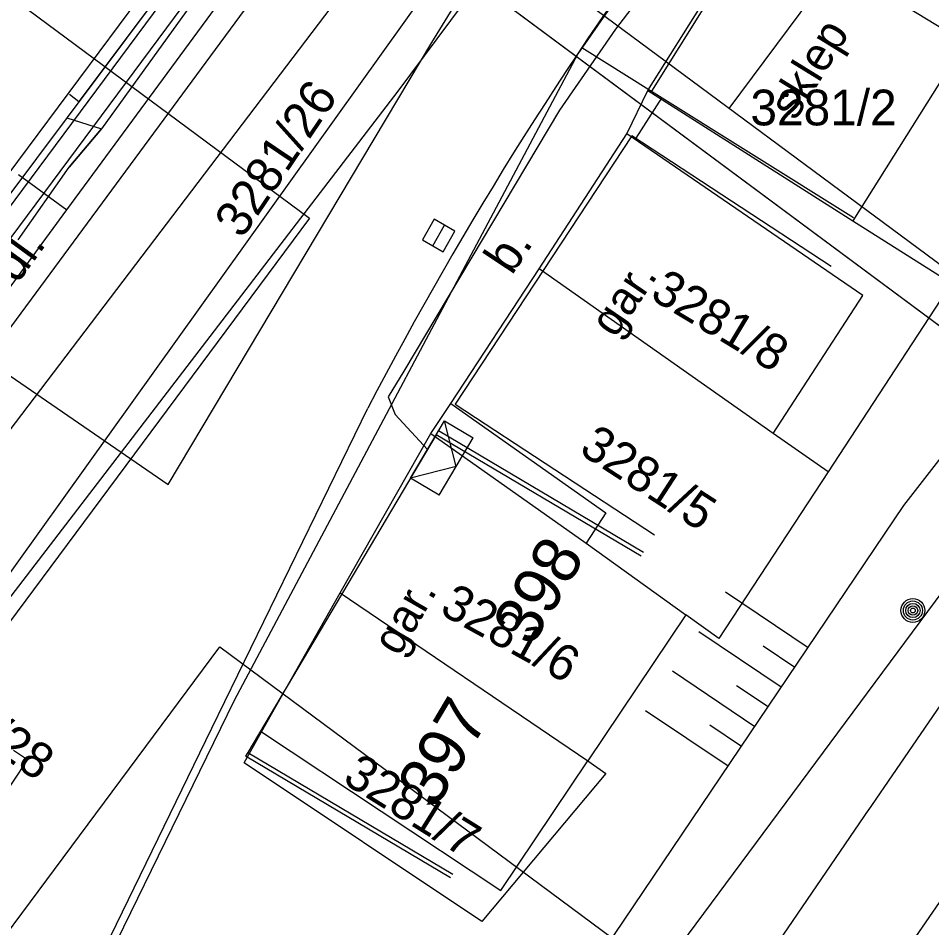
# Model space of a CAD drawing. Extents: x -601580 to 4, y -1204314 to 4.
# Drawn here: x -600277 to -600257.84, y -1203789.47 to -1203770.38 of the extents above; entities that cross this region are included whole.
import ezdxf

# ---------------------------------------------------------------- set-up
doc = ezdxf.new("R2010")
doc.units = 0
for name, color, linetype in [('00-EON NN', 7, 'Continuous'), ('00-INNOGY-NTL', 7, 'Continuous'), ('00-KN-HRANICE PARCEL', 7, 'Continuous'), ('00-KN-PARC. CISLA', 7, 'Continuous'), ('00-KN-VNITRNI KRESBA', 7, 'Continuous'), ('00-POLOHOPIS', 7, 'Continuous'), ('00-RAZÍTKO', 7, 'Continuous'), ('00-SITE KOM. KABEL', 7, 'Continuous'), ('00-VAK-KANAL-POTRUBI', 7, 'Continuous'), ('00-VAK-VODA-RAD IGIS', 7, 'Continuous'), ('11-REKONSTRUKCE KANALIZACE POPIS', 7, 'Continuous'), ('11-REKONSTRUKCE VODOVOD POPIS', 7, 'Continuous'), ('Vrstva 25', 7, 'Continuous'), ('Vrstva 27', 7, 'Continuous'), ('Vrstva 6', 7, 'Continuous'), ('Vrstva 9', 7, 'Continuous')]:
    doc.layers.add(name, color=color, linetype=linetype)

# ---------------------------------------------------------------- blocks, each defined once
blk = doc.blocks.new('6.30_50')
at = {"layer": 'Vrstva 27'}
blk.add_line((-0.25, 0), (0.25, 0), dxfattribs=at)
blk.add_lwpolyline([(-0.25, -0.25), (0.25, -0.25), (0.25, 0.25), (-0.25, 0.25)], close=True, dxfattribs=at)
blk = doc.blocks.new('6.01A_1056')
at = {"layer": 'Vrstva 25'}
for radius in [0.25, 0.2, 0.15, 0.1, 0.05]:
    blk.add_circle((0, 0), radius, dxfattribs=at)
blk = doc.blocks.new('VCHOD_1572')
at = {"layer": 'Vrstva 6'}
blk.add_line((0, 0.25), (0, 0), dxfattribs=at)
blk = doc.blocks.new('NN630')
at = {"layer": 'Vrstva 9'}
for points in [[(-3, -700), (-703, 0)], [(-703, -700), (-703, 0), (697, 0), (697, -700)], [(-3, -700), (697, 0)], [(-703, -700), (697, -700)]]:
    blk.add_lwpolyline(points, dxfattribs=at)

msp = doc.modelspace()

# ---------------------------------------------------------------- linework, layer by layer
at = {"layer": '00-EON NN'}
for points in [[(-600252.857, -1203744.996), (-600259.048, -1203754.786), (-600265.34, -1203759.062), (-600294.932, -1203798.94), (-600294.8, -1203799.42), (-600294.6, -1203799.71), (-600294.639, -1203800.117), (-600301.927, -1203809.794), (-600302.189, -1203809.81)], [(-600295.452, -1203798.97), (-600287.485, -1203788.234), (-600287.573, -1203788.171), (-600287.572, -1203787.922), (-600287.341, -1203787.853), (-600287.247, -1203787.913), (-600282.123, -1203781.008), (-600282.23, -1203780.938), (-600282.206, -1203780.697), (-600282.003, -1203780.612), (-600281.885, -1203780.687), (-600273.294, -1203769.109), (-600273.288, -1203768.864), (-600273.055, -1203768.788), (-600270.904, -1203765.889), (-600270.944, -1203765.611), (-600270.666, -1203765.567), (-600265.625, -1203758.774), (-600259.342, -1203754.503), (-600253.303, -1203744.952)], [(-600247.342, -1203745.533), (-600250.88, -1203751.15), (-600250.806, -1203751.444), (-600251.09, -1203751.45), (-600252.06, -1203752.67), (-600252.81, -1203753.78), (-600254.88, -1203757.09), (-600259.8, -1203764.05), (-600262.84, -1203768.48), (-600264.47, -1203770.61), (-600265.64, -1203772.31), (-600268.91, -1203777.79), (-600269.24, -1203778.33), (-600269.09, -1203778.7), (-600268.412, -1203779.43)]]:
    msp.add_lwpolyline(points, dxfattribs=at)
at = {"layer": '00-INNOGY-NTL'}
msp.add_line((-600276.99, -1203773.66), (-600275.98, -1203774.4), dxfattribs=at)
msp.add_lwpolyline([(-600295.95, -1203801.21), (-600295.65, -1203800.81), (-600287.36, -1203789.82), (-600286.53, -1203788.7), (-600278.7, -1203778.11), (-600278.55, -1203777.91), (-600275.98, -1203774.4), (-600270.38, -1203766.79), (-600268.42, -1203764.21), (-600266.21, -1203761.3), (-600264.99, -1203760.1), (-600261.02, -1203756.81), (-600258.4, -1203754.89), (-600252.86, -1203745.77), (-600247.26, -1203737.18), (-600244.78, -1203732.86), (-600245.17, -1203730.96), (-600245.99, -1203727.04), (-600245.48, -1203726.22)], dxfattribs=at)
at = {"layer": '00-KN-HRANICE PARCEL'}
for p, q in [((-600279.28, -1203776.44), (-600272.98, -1203767.97)), ((-600263.79, -1203771.9), (-600261.5, -1203768.23)), ((-600257.14, -1203770.89), (-600258.91, -1203769.81)), ((-600257.14, -1203770.89), (-600259.49, -1203774.63)), ((-600264.23, -1203772.81), (-600263.79, -1203771.9)), ((-600263.79, -1203771.9), (-600259.49, -1203774.63)), ((-600266.07, -1203775.64), (-600264.23, -1203772.81)), ((-600261.16, -1203779.1), (-600266.07, -1203775.64)), ((-600270.24, -1203782.44), (-600268.34, -1203779.1)), ((-600260.01, -1203779.9), (-600261.16, -1203779.1)), ((-600271.89, -1203785.36), (-600270.24, -1203782.44)), ((-600270.24, -1203782.44), (-600265.05, -1203785.97)), ((-600262.99, -1203782.9), (-600265.05, -1203785.97))]:
    msp.add_line(p, q, dxfattribs=at)
for points in [[(-600279.28, -1203776.44), (-600273.85, -1203780.17), (-600268.32, -1203770.89), (-600265.85, -1203766.87), (-600263.12, -1203761.89), (-600266.58, -1203759.37)], [(-600249.28, -1203766.8), (-600249.18, -1203771.13), (-600257.3, -1203781.99), (-600286.42, -1203821.27)], [(-600262.64, -1203767.37), (-600265.26, -1203771.13), (-600272.47, -1203784.7), (-600286.83, -1203814.12), (-600287.84, -1203817.36), (-600287.76, -1203819.53), (-600286.42, -1203821.27)], [(-600261.16, -1203779.1), (-600259.28, -1203776.2), (-600264.23, -1203772.81)], [(-600259.49, -1203774.63), (-600257.42, -1203775.94), (-600260.01, -1203779.9)], [(-600268.34, -1203779.1), (-600267.92, -1203778.47), (-600266.07, -1203775.64)], [(-600268.34, -1203779.1), (-600265.08, -1203781.4), (-600262.99, -1203782.9)], [(-600260.01, -1203779.9), (-600262.3, -1203783.4), (-600262.99, -1203782.9)], [(-600265.05, -1203785.97), (-600264.67, -1203786.23), (-600267.27, -1203789.34), (-600272.26, -1203786.01), (-600271.89, -1203785.36)], [(-600271.89, -1203785.36), (-600266.87, -1203788.69), (-600265.05, -1203785.97)]]:
    msp.add_lwpolyline(points, dxfattribs=at)
at = {"layer": '00-KN-VNITRNI KRESBA'}
for p, q in [((-600267.92, -1203778.47), (-600264.67, -1203780.76)), ((-600264.67, -1203780.76), (-600265.08, -1203781.4))]:
    msp.add_line(p, q, dxfattribs=at)
at = {"layer": '00-POLOHOPIS'}
for p, q in [((-600265.374, -1203760.864), (-600283.066, -1203784.884)), ((-600273.801, -1203769.554), (-600275.722, -1203772.126)), ((-600265.176, -1203770.997), (-600263.716, -1203771.909)), ((-600263.495, -1203772.043), (-600264.041, -1203772.895)), ((-600258.42, -1203780.606), (-600251.983, -1203772.323)), ((-600249.579, -1203773.011), (-600259.175, -1203787.013)), ((-600272.936, -1203785.282), (-600269.662, -1203778.567)), ((-600268.229, -1203779.122), (-600268.183, -1203779.044)), ((-600263.882, -1203781.593), (-600268.183, -1203779.044)), ((-600275.448, -1203805.851), (-600258.42, -1203780.606)), ((-600262.158, -1203782.422), (-600260.43, -1203783.587)), ((-600262.717, -1203783.251), (-600260.99, -1203784.416)), ((-600261.37, -1203783.556), (-600260.71, -1203784.001)), ((-600263.276, -1203784.08), (-600261.549, -1203785.245)), ((-600261.929, -1203784.385), (-600261.269, -1203784.83)), ((-600263.836, -1203784.909), (-600262.108, -1203786.074)), ((-600262.488, -1203785.214), (-600261.828, -1203785.659)), ((-600275.701, -1203790.96), (-600272.936, -1203785.282)), ((-600277.095, -1203785.743), (-600276.804, -1203785.937)), ((-600272.183, -1203785.795), (-600272.229, -1203785.872)), ((-600276.804, -1203785.937), (-600278.935, -1203789.149)), ((-600267.927, -1203788.421), (-600272.229, -1203785.872)), ((-600259.154, -1203786.982), (-600282.637, -1203821.382))]:
    msp.add_line(p, q, dxfattribs=at)
for points in [[(-600276.901, -1203765.244), (-600272.838, -1203768.264), (-600279.127, -1203776.684), (-600282.733, -1203773.992)], [(-600258.634, -1203769.979), (-600261.42, -1203768.237), (-600263.716, -1203771.909), (-600259.476, -1203774.56)], [(-600259.945, -1203775.593), (-600264.123, -1203772.846), (-600267.828, -1203778.48), (-600263.65, -1203781.227)], [(-600263.927, -1203781.671), (-600268.229, -1203779.122), (-600272.183, -1203785.795), (-600267.881, -1203788.344)]]:
    msp.add_lwpolyline(points, dxfattribs=at)
msp.add_arc((-600199.5, -1203815.029), 79.07, 143.00289, 152.54008, dxfattribs=at)
at = {"layer": '00-RAZÍTKO'}
for p, q in [((-600262.081, -1203772.278), (-600205.546, -1203696.113)), ((-600245.504, -1203784.583), (-600276.866, -1203761.304))]:
    msp.add_line(p, q, dxfattribs=at)
for points in [[(-600188.969, -1203708.417), (-600246.123, -1203785.417), (-600325.417, -1203726.559), (-600268.263, -1203649.56)], [(-600188.969, -1203708.417), (-600246.123, -1203785.417), (-600310.751, -1203737.445), (-600253.597, -1203660.446)]]:
    msp.add_lwpolyline(points, close=True, dxfattribs=at)
at = {"layer": '00-SITE KOM. KABEL'}
for points in [[(-600271.01, -1203766.87), (-600271.21, -1203767.09), (-600275.25, -1203772.7)], [(-600271.21, -1203767.09), (-600275.25, -1203772.7)], [(-600275.98, -1203772.47), (-600275.25, -1203772.7)], [(-600277, -1203775.03), (-600275.93, -1203773.51), (-600275.25, -1203772.7)], [(-600275.25, -1203772.7), (-600275.93, -1203773.51)]]:
    msp.add_lwpolyline(points, dxfattribs=at)
at = {"layer": '00-VAK-KANAL-POTRUBI'}
for points in [[(-600263.646, -1203763.102), (-600288.953, -1203798.483), (-600301.999, -1203816.723)], [(-600250.599, -1203778.658), (-600276.7, -1203816.55)]]:
    msp.add_lwpolyline(points, dxfattribs=at)
at = {"layer": '00-VAK-VODA-RAD IGIS'}
for points in [[(-600237.019, -1203720.962), (-600247.043, -1203738.764), (-600258.194, -1203754.202), (-600265.436, -1203763.558), (-600282.474, -1203785.988), (-600297.618, -1203805.864)], [(-600294.521, -1203805.29), (-600277.888, -1203783.466), (-600269.03, -1203771.912), (-600239.859, -1203732.742), (-600236.89, -1203728.365)]]:
    msp.add_lwpolyline(points, dxfattribs=at)
at = {"layer": '11-REKONSTRUKCE KANALIZACE POPIS'}
msp.add_lwpolyline([(-600329.538, -1203831.409), (-600281.505, -1203766.698), (-600270.889, -1203774.578), (-600318.922, -1203839.289)], close=True, dxfattribs=at)
msp.add_lwpolyline([(-600329.538, -1203831.409), (-600281.505, -1203766.698), (-600270.889, -1203774.578), (-600318.922, -1203839.289)], close=True, dxfattribs=at)
at = {"layer": '11-REKONSTRUKCE VODOVOD POPIS'}
msp.add_lwpolyline([(-600316.018, -1203841.848), (-600272.765, -1203783.577), (-600262.149, -1203791.457), (-600305.402, -1203849.728)], close=True, dxfattribs=at)
msp.add_lwpolyline([(-600316.018, -1203841.848), (-600272.765, -1203783.577), (-600262.149, -1203791.457), (-600305.402, -1203849.728)], close=True, dxfattribs=at)

# ---------------------------------------------------------------- block references
at = {"layer": '00-EON NN', "xscale": 0.001, "yscale": 0.0010000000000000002, "rotation": 59.351686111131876}
msp.add_blockref('NN630', (-600268.412, -1203779.43), dxfattribs=at)
at = {"layer": '00-POLOHOPIS'}
for name, p, xscale, yscale, rotation in [('VCHOD_1572', (-600275.722, -1203772.126), 1.00000012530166, 1.00000012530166, 53.24434819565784), ('6.30_50', (-600268.177, -1203774.942), 0.9999993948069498, 0.9999993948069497, 60.05387931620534), ('6.01A_1056', (-600258.23, -1203782.812), 1.00000188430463, 1.00000188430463, 150.0012946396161)]:
    msp.add_blockref(name, p, dxfattribs=dict(at, xscale=xscale, yscale=yscale, rotation=rotation))

# ---------------------------------------------------------------- texts
at = {"layer": '00-KN-PARC. CISLA'}
for s, rotation, p in [('3281/26', 56, (-600272.302, -1203775.029)), ('3281/8', 329, (-600263.772, -1203776.251)), ('3281/5', 327, (-600265.258, -1203779.498)), ('3281/6', 331, (-600268.185, -1203782.865)), ('3281/28', 325, (-600279.564, -1203784.328)), ('3281/7', 328, (-600270.22, -1203786.41))]:
    msp.add_text(s, height=0.75, rotation=rotation, dxfattribs=at).set_placement(p)
msp.add_text('3281/2', height=0.75, dxfattribs=at).set_placement((-600261.638, -1203772.63))
at = {"layer": '00-POLOHOPIS'}
for s, height, rotation, p in [('sklep', 0.7, 58.3374, (-600260.695, -1203772.549)), ('dl.', 0.75, 53.8841, (-600277.017, -1203775.973)), ('b.', 0.75, 56.4715, (-600266.642, -1203775.794)), ('gar.', 0.7, 55.8533, (-600264.472, -1203777.112)), ('398', 1, 59.3517, (-600266.232, -1203783.598)), ('gar.', 0.7, 59.9468, (-600269.004, -1203783.794)), ('397', 1, 59.3517, (-600268.235, -1203786.979))]:
    msp.add_text(s, height=height, rotation=rotation, dxfattribs=at).set_placement(p)

doc.saveas('drawing.dxf')
